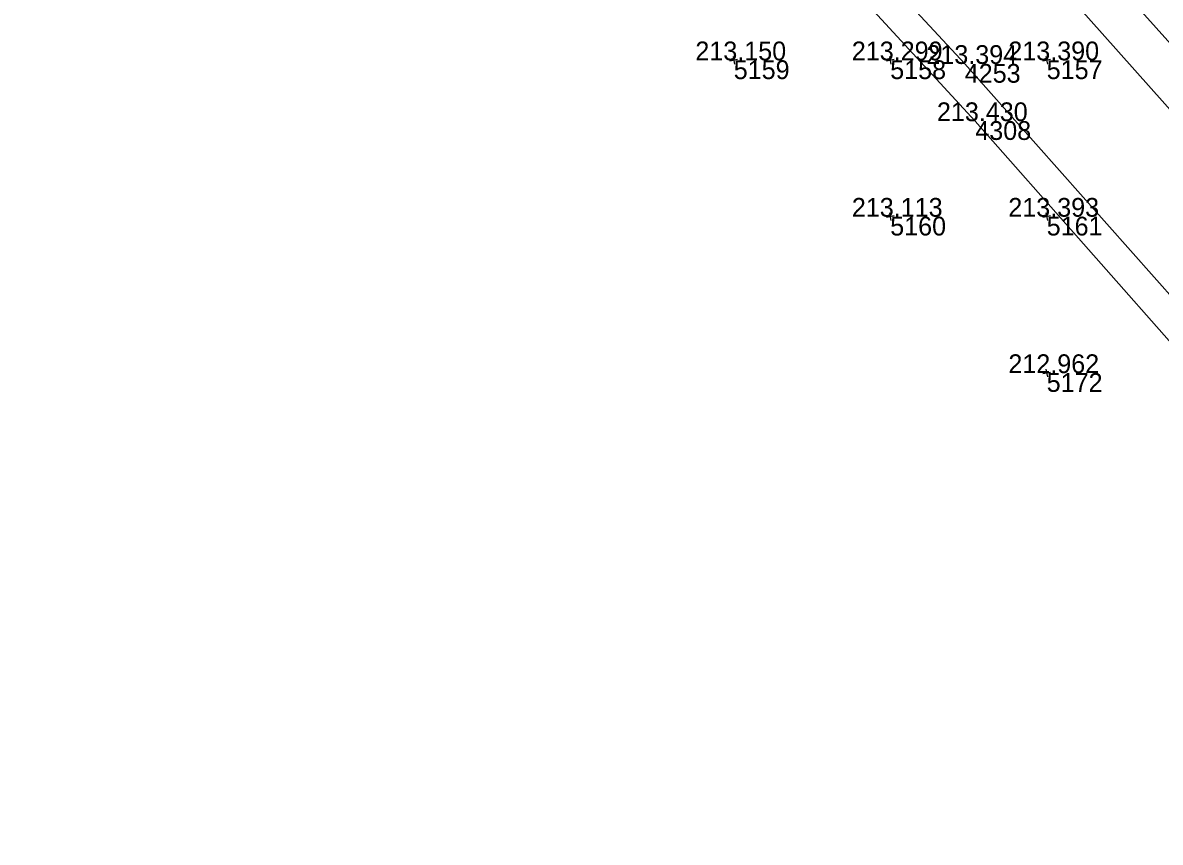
# Model space of a CAD drawing. Extents: x -556590 to -554855, y -1137918 to -1135717.
# Drawn here: x -555845.4 to -555772.7, y -1136370 to -1136317.6 of the extents above; entities that cross this region are included whole.
import ezdxf

# ---------------------------------------------------------------- set-up
doc = ezdxf.new("R2010")
doc.units = 0
for name, color, linetype in [('Vrstva 49', 7, 'Continuous'), ('Vrstva 51', 7, 'Continuous'), ('Vrstva 60', 7, 'Continuous'), ('Vrstva 61', 7, 'Continuous')]:
    doc.layers.add(name, color=color, linetype=linetype)

msp = doc.modelspace()

# ---------------------------------------------------------------- linework, layer by layer
at = {"layer": 'Vrstva 49'}
for p, q in [((-555799.754, -1136319.953), (-555800.246, -1136320.047)), ((-555800.047, -1136319.754), (-555799.953, -1136320.246)), ((-555789.754, -1136319.953), (-555790.246, -1136320.047)), ((-555790.047, -1136319.754), (-555789.953, -1136320.246)), ((-555779.754, -1136319.953), (-555780.246, -1136320.047)), ((-555780.047, -1136319.754), (-555779.953, -1136320.246)), ((-555789.754, -1136329.953), (-555790.246, -1136330.047)), ((-555790.047, -1136329.754), (-555789.953, -1136330.246)), ((-555779.754, -1136329.953), (-555780.246, -1136330.047)), ((-555780.047, -1136329.754), (-555779.953, -1136330.246)), ((-555780.047, -1136339.754), (-555779.953, -1136340.246)), ((-555779.754, -1136339.953), (-555780.246, -1136340.047))]:
    msp.add_line(p, q, dxfattribs=at)
for points in [[(-555736.771, -1136359.665), (-555749.338, -1136344.71), (-555764.071, -1136327.878), (-555781.923, -1136307.954), (-555797.677, -1136289.199), (-555815.137, -1136269.492), (-555833.114, -1136250.232)], [(-555834.964, -1136252.165), (-555824.94, -1136262.729), (-555809.984, -1136279.569), (-555796.116, -1136296.082), (-555780.292, -1136313.951), (-555764.608, -1136331.585), (-555746.999, -1136352.114), (-555735.716, -1136364.999)]]:
    msp.add_lwpolyline(points, dxfattribs=at)
at = {"layer": 'Vrstva 51'}
for points in [[(-555743.133, -1136368.314), (-555758.237, -1136350.909), (-555770.103, -1136337.273), (-555785.237, -1136320.231), (-555800.202, -1136304.081), (-555818.312, -1136284.844), (-555838.398, -1136263.585), (-555844.031, -1136257.565)], [(-555845.438, -1136259.043), (-555837.133, -1136267.768), (-555822.79, -1136282.856), (-555802.014, -1136304.92), (-555784.563, -1136323.89), (-555763.8, -1136347.422), (-555744.231, -1136369.998)]]:
    msp.add_lwpolyline(points, dxfattribs=at)
at = {"layer": 'Vrstva 60'}
for p, q in [((-555800, -1136320), (-555800, -1136320)), ((-555790, -1136320), (-555790, -1136320)), ((-555780, -1136320), (-555780, -1136320)), ((-555785.237, -1136320.231), (-555785.237, -1136320.231)), ((-555784.563, -1136323.89), (-555784.563, -1136323.89)), ((-555790, -1136330), (-555790, -1136330)), ((-555780, -1136330), (-555780, -1136330)), ((-555780, -1136340), (-555780, -1136340))]:
    msp.add_line(p, q, dxfattribs=at)

# ---------------------------------------------------------------- texts
for s, p in [('5159', (-555800, -1136321.2)), ('5158', (-555790, -1136321.2)), ('5157', (-555780, -1136321.2)), ('4253', (-555785.237, -1136321.431)), ('4308', (-555784.563, -1136325.09)), ('5160', (-555790, -1136331.2)), ('5161', (-555780, -1136331.2)), ('5172', (-555780, -1136341.2))]:
    msp.add_text(s, height=1.2, dxfattribs=at).set_placement(p)
at = {"layer": 'Vrstva 61'}
for s, p in [('213.150', (-555802.451, -1136320)), ('213.299', (-555792.454, -1136320)), ('213.394', (-555787.688, -1136320.231)), ('213.390', (-555782.451, -1136320)), ('213.430', (-555787.014, -1136323.89)), ('213.113', (-555792.452, -1136330)), ('213.393', (-555782.452, -1136330)), ('212.962', (-555782.448, -1136340))]:
    msp.add_text(s, height=1.2, dxfattribs=at).set_placement(p)

doc.saveas('drawing.dxf')
